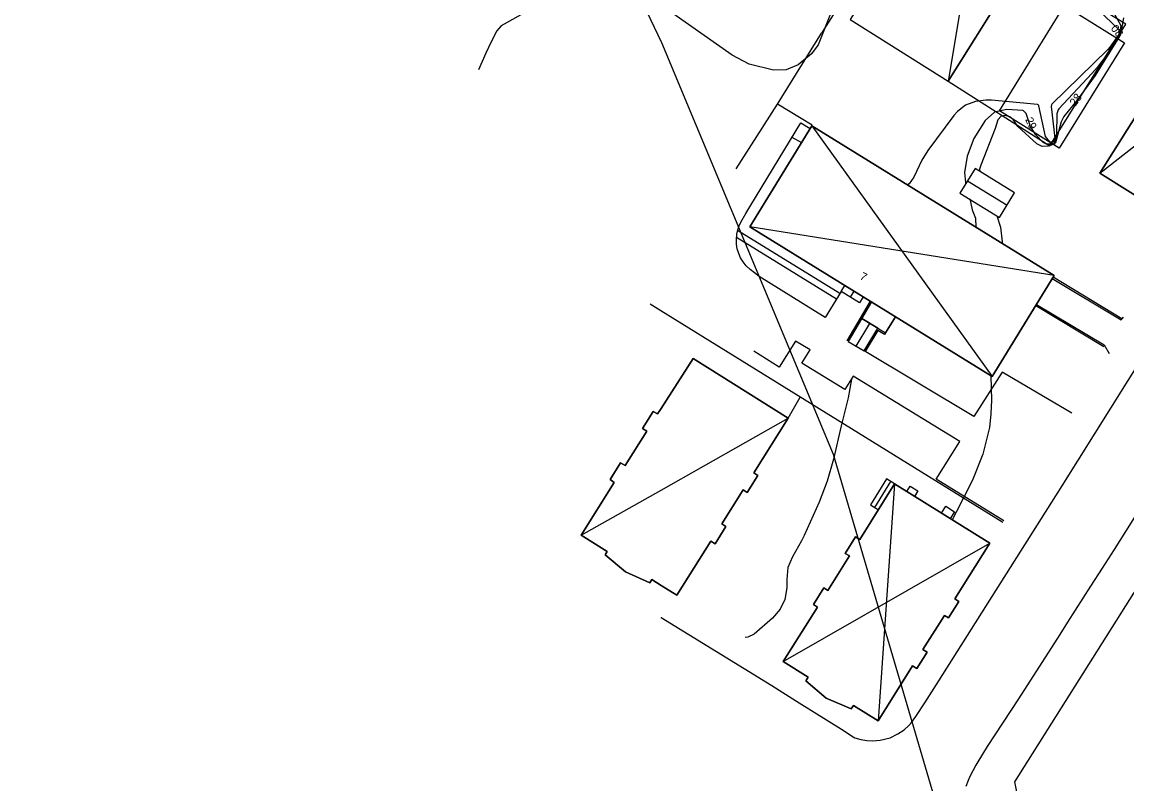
# Model space of a CAD drawing. Extents: x 67169 to 69652, y 20189 to 22818.
# Drawn here: x 69163.3 to 69301.4, y 21050.3 to 21145.5 of the extents above; entities that cross this region are included whole.
import ezdxf

# ---------------------------------------------------------------- set-up
doc = ezdxf.new("R2010")
doc.units = 0
for name, color, linetype in [('BYGGNAD_HUSLIV', 7, 'Continuous'), ('BYGGNAD_HUSLIV 11', 7, 'Continuous'), ('BYGGNADSDETALJER', 7, 'Continuous'), ('BYGGNADSDETALJER 19', 7, 'Continuous'), ('BYGGNADSSYMBOLER', 7, 'Continuous'), ('BYGGNADSSYMBOLER 30', 7, 'Continuous'), ('HOJDKURVOR_2014', 7, 'Continuous'), ('HOJDKURVOR_2014 5M', 7, 'Continuous'), ('HOJDKURVOR_TEXTER_2014', 7, 'Continuous'), ('Instruktioner', 7, 'Continuous'), ('JARNVAGAR', 7, 'Continuous'), ('MUR_STAKET', 7, 'Continuous'), ('MUR_STAKET_SYMBOL', 7, 'Continuous'), ('Std_Ritningsstämpel', 7, 'Continuous'), ('VAGAR 121', 7, 'Continuous'), ('VAGAR 123', 7, 'Continuous')]:
    doc.layers.add(name, color=color, linetype=linetype)

msp = doc.modelspace()

# ---------------------------------------------------------------- linework, layer by layer
at = {"layer": 'BYGGNAD_HUSLIV'}
msp.add_line((69242.68, 21096.53), (69242.99, 21096.96), dxfattribs=at)
for points in [[(69317.37, 21157.37), (69328.38, 21150.49), (69309.01, 21119.71), (69298, 21126.59), (69317.37, 21157.37)], [(69293.56, 21147.57), (69301.05, 21142.9), (69292.91, 21129.74), (69285.43, 21134.41), (69293.56, 21147.57)], [(69261.97, 21132.53), (69292.27, 21113.82), (69284.53, 21101.19), (69254.22, 21119.9), (69261.97, 21132.53)], [(69242.99, 21096.96), (69243.13, 21097.18), (69247.16, 21103.43), (69259.04, 21095.98), (69254.74, 21089.15), (69255.25, 21088.83), (69253.9, 21086.69), (69253.39, 21087.01), (69250.72, 21082.76), (69251.23, 21082.44), (69249.88, 21080.3), (69249.37, 21080.62), (69245.12, 21073.85), (69243.14, 21075.09)], [(69243.14, 21075.09), (69241.98, 21075.82), (69241.72, 21075.41), (69238.68, 21076.77), (69236.14, 21078.92), (69236.39, 21079.32), (69233.14, 21081.37), (69237.28, 21087.96), (69236.77, 21088.34), (69238.08, 21090.42), (69238.64, 21090.09), (69241.34, 21094.35), (69240.82, 21094.71), (69242.17, 21096.83), (69242.68, 21096.53)], [(69272.33, 21087.76), (69284.22, 21080.36), (69279.86, 21073.41), (69280.37, 21073.09), (69279.07, 21071.02), (69278.56, 21071.33), (69275.87, 21067.07), (69276.38, 21066.76), (69275.09, 21064.7), (69274.58, 21065.02), (69270.28, 21058.15), (69267.18, 21060.09), (69266.9, 21059.64), (69263.79, 21061.01), (69261.23, 21063.17), (69261.51, 21063.62), (69258.4, 21065.56), (69262.68, 21072.38), (69262.17, 21072.7), (69263.47, 21074.77), (69263.98, 21074.45), (69266.68, 21078.76), (69266.16, 21079.09), (69267.46, 21081.15), (69267.98, 21080.82), (69272.33, 21087.76)]]:
    msp.add_lwpolyline(points, dxfattribs=at)
at = {"layer": 'BYGGNAD_HUSLIV 11'}
msp.add_line((69242.68, 21096.53), (69242.99, 21096.96), dxfattribs=at)
for points in [[(69317.37, 21157.37), (69328.38, 21150.49), (69309.01, 21119.71), (69298, 21126.59), (69317.37, 21157.37)], [(69261.97, 21132.53), (69292.27, 21113.82), (69284.53, 21101.19), (69254.22, 21119.9), (69261.97, 21132.53)], [(69242.99, 21096.96), (69243.13, 21097.18), (69247.16, 21103.43), (69259.04, 21095.98), (69254.74, 21089.15), (69255.25, 21088.83), (69253.9, 21086.69), (69253.39, 21087.01), (69250.72, 21082.76), (69251.23, 21082.44), (69249.88, 21080.3), (69249.37, 21080.62), (69245.12, 21073.85), (69243.14, 21075.09)], [(69243.14, 21075.09), (69241.98, 21075.82), (69241.72, 21075.41), (69238.68, 21076.77), (69236.14, 21078.92), (69236.39, 21079.32), (69233.14, 21081.37), (69237.28, 21087.96), (69236.77, 21088.34), (69238.08, 21090.42), (69238.64, 21090.09), (69241.34, 21094.35), (69240.82, 21094.71), (69242.17, 21096.83), (69242.68, 21096.53)], [(69272.33, 21087.76), (69284.22, 21080.36), (69279.86, 21073.41), (69280.37, 21073.09), (69279.07, 21071.02), (69278.56, 21071.33), (69275.87, 21067.07), (69276.38, 21066.76), (69275.09, 21064.7), (69274.58, 21065.02), (69270.28, 21058.15), (69267.18, 21060.09), (69266.9, 21059.64), (69263.79, 21061.01), (69261.23, 21063.17), (69261.51, 21063.62), (69258.4, 21065.56), (69262.68, 21072.38), (69262.17, 21072.7), (69263.47, 21074.77), (69263.98, 21074.45), (69266.68, 21078.76), (69266.16, 21079.09), (69267.46, 21081.15), (69267.98, 21080.82), (69272.33, 21087.76)]]:
    msp.add_lwpolyline(points, dxfattribs=at)
at = {"layer": 'BYGGNADSDETALJER'}
msp.add_line((69266.11, 21112.56), (69268.4, 21111.14), dxfattribs=at)
for points in [[(69268.4, 21111.14), (69267.94, 21110.42), (69265.64, 21111.82), (69266.11, 21112.56)], [(69269.42, 21110.51), (69266.54, 21105.55), (69268.51, 21104.39), (69270.23, 21107.22), (69268.22, 21108.45)], [(69268.22, 21108.45), (69271.18, 21106.64), (69272.45, 21108.64)], [(69270.3, 21084.53), (69272.33, 21087.76), (69271.32, 21088.4), (69269.3, 21085.14), (69270.3, 21084.53)], [(69274.83, 21086.21), (69273.84, 21086.82), (69274.26, 21087.48), (69275.24, 21086.89), (69274.83, 21086.21)], [(69279.28, 21083.43), (69278.17, 21084.12), (69278.73, 21084.97), (69279.82, 21084.3), (69279.28, 21083.43)]]:
    msp.add_lwpolyline(points, dxfattribs=at)
at = {"layer": 'BYGGNADSDETALJER 19'}
msp.add_lwpolyline([(69268.22, 21108.45), (69271.18, 21106.64), (69272.45, 21108.64)], dxfattribs=at)
at = {"layer": 'BYGGNADSSYMBOLER'}
for p, q in [((69285.23, 21175.26), (69279.02, 21138.12)), ((69298, 21126.59), (69328.38, 21150.49)), ((69261.97, 21132.53), (69284.53, 21101.19)), ((69281.44, 21125.66), (69286.38, 21122.61)), ((69292.27, 21113.82), (69254.22, 21119.9)), ((69267.25, 21111.85), (69266.79, 21111.12)), ((69267.25, 21111.85), (69267.25, 21111.85)), ((69267.52, 21104.97), (69269.23, 21107.83)), ((69267.52, 21104.97), (69267.52, 21104.97)), ((69271.83, 21088.08), (69269.8, 21084.83)), ((69272.33, 21087.76), (69270.28, 21058.15)), ((69271.83, 21088.08), (69271.83, 21088.08)), ((69258.4, 21065.56), (69284.22, 21080.36))]:
    msp.add_line(p, q, dxfattribs=at)
msp.add_lwpolyline([(69233.15, 21081.36), (69243.13, 21087), (69259.04, 21095.98)], dxfattribs=at)
at = {"layer": 'BYGGNADSSYMBOLER 30'}
for p, q in [((69285.23, 21175.26), (69279.02, 21138.12)), ((69298, 21126.59), (69328.38, 21150.49)), ((69261.97, 21132.53), (69284.53, 21101.19)), ((69292.27, 21113.82), (69254.22, 21119.9)), ((69272.33, 21087.76), (69270.28, 21058.15)), ((69258.4, 21065.56), (69284.22, 21080.36))]:
    msp.add_line(p, q, dxfattribs=at)
msp.add_lwpolyline([(69233.15, 21081.36), (69243.13, 21087), (69259.04, 21095.98)], dxfattribs=at)
at = {"layer": 'HOJDKURVOR_2014'}
for points in [[(69264.48, 21146.95), (69262.78, 21142.63), (69261.92, 21141.51), (69260.26, 21140.16), (69258.79, 21139.51), (69257.18, 21139.46), (69254.13, 21140.22), (69252.02, 21141.37), (69243.06, 21147.63)], [(69298.72, 21148.49), (69300.61, 21145.06), (69300.44, 21143.9), (69298.85, 21141.39), (69297.64, 21139.82), (69296.99, 21139.07), (69292.87, 21134.63), (69292.78, 21134.53), (69292.59, 21134.04), (69292.57, 21131.47), (69292.34, 21130.49), (69292.28, 21130.41), (69291.78, 21130.24), (69291.31, 21130.22), (69290.89, 21130.44), (69289.97, 21131.41), (69289.33, 21132.43), (69288.76, 21134.06), (69288.45, 21134.39), (69288.35, 21134.44), (69286.35, 21134.56), (69284.83, 21134.22), (69283.66, 21133.19), (69282.22, 21130.94), (69281.4, 21128.75), (69281.05, 21126.69), (69281.2, 21125.44), (69281.23, 21125.31)], [(69225.63, 21146.39), (69223.16, 21145.01), (69222.62, 21144.41), (69221.91, 21143.03), (69221.24, 21141.62), (69220.33, 21139.54)], [(69300.95, 21146.01), (69300.59, 21144.09), (69300.46, 21143.74), (69300.4, 21143.63), (69298.08, 21139.9), (69297.38, 21138.81), (69295.09, 21135.7), (69293.47, 21133.68), (69293.15, 21133.03), (69292.42, 21130.41), (69292.41, 21130.39), (69292.3, 21130.25), (69292.28, 21130.25), (69291.52, 21129.99), (69290.78, 21129.95), (69290.12, 21130.29), (69287.75, 21132.45), (69287.15, 21133.31), (69286.72, 21133.66), (69286.2, 21133.82), (69285.65, 21133.75), (69285.22, 21133.26), (69284.88, 21132.17), (69283.1, 21127.59), (69282.95, 21127.1), (69282.96, 21126.83)], [(69281.71, 21123.38), (69282.04, 21122.02), (69282.44, 21120.97), (69282.47, 21119.87)], [(69285.12, 21121.27), (69285.57, 21119.85), (69285.78, 21118.04), (69285.78, 21117.83)], [(69266.92, 21100.84), (69266.51, 21098.52), (69265.65, 21095.04), (69264.67, 21090.86), (69263.91, 21088.12), (69262.88, 21085.47), (69261.02, 21081.34), (69260.69, 21080.65), (69259.58, 21078.66), (69259, 21077.31), (69258.84, 21075.84), (69258.86, 21074.76), (69258.6, 21073.32), (69258.04, 21072.1), (69257.05, 21070.98), (69254.79, 21068.98), (69253.99, 21068.63), (69253.64, 21068.59)], [(69284.37, 21101.29), (69284.42, 21098.25), (69284.36, 21096.53), (69284.18, 21094.82), (69283.34, 21091.49), (69282.07, 21088.25), (69280.06, 21084.32), (69279.52, 21083.29)]]:
    msp.add_lwpolyline(points, dxfattribs=at)
at = {"layer": 'HOJDKURVOR_2014 5M'}
msp.add_lwpolyline([(69297.82, 21146.97), (69300.31, 21144.61), (69300.42, 21144.42), (69300.43, 21144.19), (69300.37, 21143.93), (69299.25, 21142.36), (69298.98, 21142.07), (69292, 21135.25), (69291.93, 21135.16), (69291.89, 21134.93), (69292.36, 21131), (69292.28, 21130.6), (69292.25, 21130.57), (69291.93, 21130.48), (69291.75, 21130.53), (69291.19, 21131.17), (69290.37, 21135.04), (69290.36, 21135.06), (69290.26, 21135.15), (69290.17, 21135.18), (69284.42, 21135.71), (69283.75, 21135.73), (69282.44, 21135.56), (69281.2, 21135.09), (69280.17, 21134.32), (69279.73, 21133.82), (69276.49, 21129.43), (69275.73, 21128.24), (69274.72, 21126.11), (69274.16, 21125.26), (69273.96, 21125.13)], dxfattribs=at)
at = {"layer": 'JARNVAGAR'}
msp.add_lwpolyline([(69162.71, 21269.58), (69192.52, 21230.99), (69216.76, 21192.72), (69236.42, 21157.17), (69243.2, 21142.94), (69264.66, 21091.47), (69285.76, 21019.69), (69301.99, 20965.18), (69320.92, 20901.49), (69337.69, 20844.28)], dxfattribs=at)
at = {"layer": 'MUR_STAKET'}
for p, q in [((69284.59, 21177.99), (69263.19, 21144.09)), ((69262.01, 21132.59), (69257.69, 21135.25)), ((69269.26, 21110.61), (69266.37, 21105.64)), ((69269.26, 21110.61), (69266.37, 21105.64)), ((69289.96, 21110.05), (69298.49, 21104.96)), ((69272.45, 21108.64), (69271.18, 21106.64))]:
    msp.add_line(p, q, dxfattribs=at)
for points in [[(69252.51, 21127.15), (69257.69, 21135.25), (69263.19, 21144.09)], [(69300.88, 21108.61), (69300.75, 21108.41), (69292.14, 21113.6)], [(69285.85, 21082.93), (69243.11, 21109.4), (69241.77, 21110.23)], [(69272.45, 21108.64), (69271.18, 21106.64), (69271.06, 21106.44), (69270.23, 21106.93), (69268.64, 21104.32)], [(69271.32, 21088.4), (69269.3, 21085.14), (69270.3, 21084.53)], [(69271.32, 21088.4), (69269.3, 21085.14), (69270.3, 21084.53)], [(69322.79, 21025.8), (69287.95, 21047.64), (69287.36, 21050.54), (69309.75, 21086.07)]]:
    msp.add_lwpolyline(points, dxfattribs=at)
at = {"layer": 'MUR_STAKET_SYMBOL'}
for p, q in [((69260.66, 21140.03), (69260.66, 21140.03)), ((69260.41, 21133.57), (69260.41, 21133.57)), ((69255.12, 21131.22), (69255.12, 21131.22)), ((69268.67, 21109.59), (69268.67, 21109.59)), ((69290.87, 21109.51), (69290.87, 21109.51)), ((69267.89, 21108.26), (69267.89, 21108.26)), ((69272.04, 21107.99), (69272.04, 21107.99)), ((69272.07, 21108.03), (69272.07, 21108.03)), ((69292.12, 21108.76), (69292.12, 21108.76)), ((69293.35, 21108.02), (69293.35, 21108.02)), ((69248.12, 21106.29), (69248.12, 21106.29)), ((69267.14, 21106.96), (69267.14, 21106.96)), ((69267.23, 21107.12), (69267.23, 21107.12)), ((69270.68, 21106.66), (69270.68, 21106.66)), ((69271.39, 21106.97), (69271.39, 21106.97)), ((69294.68, 21107.23), (69294.68, 21107.23)), ((69295.97, 21106.47), (69295.97, 21106.47)), ((69266.37, 21105.64), (69266.37, 21105.64)), ((69269.48, 21105.7), (69269.48, 21105.7)), ((69297.25, 21105.7), (69297.25, 21105.7)), ((69298.49, 21104.96), (69298.49, 21104.96)), ((69264.2, 21096.33), (69264.2, 21096.33)), ((69270.3, 21086.76), (69270.3, 21086.76)), ((69271.09, 21088.04), (69271.09, 21088.04)), ((69269.55, 21085.53), (69269.55, 21085.53)), ((69270.09, 21086.42), (69270.09, 21086.42)), ((69279.79, 21086.67), (69279.79, 21086.67)), ((69269.58, 21084.96), (69269.58, 21084.96)), ((69300.71, 21071.74), (69300.71, 21071.74)), ((69299.94, 21070.51), (69299.94, 21070.51)), ((69299.12, 21069.21), (69299.12, 21069.21)), ((69298.32, 21067.94), (69298.32, 21067.94)), ((69297.56, 21066.73), (69297.56, 21066.73)), ((69296.73, 21065.41), (69296.73, 21065.41)), ((69295.95, 21064.17), (69295.95, 21064.17)), ((69295.13, 21062.88), (69295.13, 21062.88)), ((69294.33, 21061.61), (69294.33, 21061.61)), ((69293.55, 21060.36), (69293.55, 21060.36)), ((69292.03, 21057.96), (69292.03, 21057.96)), ((69292.73, 21059.06), (69292.73, 21059.06)), ((69291.27, 21056.76), (69291.27, 21056.76)), ((69290.45, 21055.46), (69290.45, 21055.46)), ((69289.66, 21054.2), (69289.66, 21054.2)), ((69288.84, 21052.89), (69288.84, 21052.89)), ((69288.05, 21051.65), (69288.05, 21051.65))]:
    msp.add_line(p, q, dxfattribs=at)
at = {"layer": 'Std_Ritningsstämpel'}
for points in [[(69266.76, 21145.82), (69279.02, 21138.11), (69297.52, 21167.57), (69285.23, 21175.26)], [(69317.37, 21157.37), (69298, 21126.59), (69309.01, 21119.71), (69328.38, 21150.49)], [(69279.02, 21138.11), (69291.73, 21130.03), (69301.23, 21145.21), (69288.39, 21153.08)], [(69261.97, 21132.53), (69254.22, 21119.9), (69284.53, 21101.19), (69292.27, 21113.82)], [(69282.39, 21127.19), (69280.5, 21124.12), (69285.43, 21121.08), (69287.32, 21124.14)], [(69243.13, 21097.18), (69242.99, 21096.96), (69242.68, 21096.53), (69242.17, 21096.83), (69240.82, 21094.71), (69241.34, 21094.35), (69238.64, 21090.09), (69238.08, 21090.42), (69236.77, 21088.34), (69237.28, 21087.96), (69233.14, 21081.37), (69236.39, 21079.32), (69236.14, 21078.92), (69238.68, 21076.77), (69241.72, 21075.41), (69241.98, 21075.82), (69243.14, 21075.09), (69245.12, 21073.85), (69249.37, 21080.62), (69249.88, 21080.3), (69251.23, 21082.44), (69250.72, 21082.76), (69253.39, 21087.01), (69253.9, 21086.69), (69255.25, 21088.83), (69254.74, 21089.15), (69259.04, 21095.98), (69247.16, 21103.43)], [(69272.33, 21087.76), (69267.98, 21080.82), (69267.46, 21081.15), (69266.16, 21079.09), (69266.68, 21078.76), (69263.98, 21074.45), (69263.47, 21074.77), (69262.17, 21072.7), (69262.68, 21072.38), (69258.4, 21065.56), (69261.51, 21063.62), (69261.23, 21063.17), (69263.79, 21061.01), (69266.9, 21059.64), (69267.18, 21060.09), (69270.28, 21058.15), (69274.58, 21065.02), (69275.09, 21064.7), (69276.38, 21066.76), (69275.87, 21067.07), (69278.56, 21071.33), (69279.07, 21071.02), (69280.37, 21073.09), (69279.86, 21073.41), (69284.22, 21080.36)]]:
    msp.add_lwpolyline(points, close=True, dxfattribs=at)
at = {"layer": 'VAGAR 121'}
for p, q in [((69260.59, 21132.91), (69261.76, 21132.19)), ((69259.5, 21131.11), (69260.68, 21130.42)), ((69259.04, 21095.98), (69260.53, 21098.61))]:
    msp.add_line(p, q, dxfattribs=at)
for points in [[(69265.64, 21111.82), (69263.63, 21108.55), (69255.39, 21113.71), (69254.81, 21114.15), (69254.28, 21114.55), (69253.77, 21115.02), (69253.39, 21115.51), (69253.08, 21116.04), (69252.85, 21116.56), (69252.67, 21117.16), (69252.58, 21117.73), (69252.55, 21118.26), (69252.6, 21118.98), (69252.72, 21119.52), (69252.88, 21120.02), (69253.09, 21120.5), (69253.73, 21121.57), (69254.36, 21122.62), (69260.59, 21132.91)], [(69292.03, 21113.43), (69300.65, 21108.27), (69300.75, 21108.41)], [(69290.05, 21110.2), (69298.54, 21105.16), (69299.15, 21104.05)], [(69285.98, 21083.14), (69277.52, 21088.37), (69280.47, 21093.08), (69267.16, 21101.22), (69266.12, 21099.57), (69260.75, 21102.88), (69261.77, 21104.53), (69259.95, 21105.61), (69257.88, 21102.35), (69254.73, 21104.35)], [(69243.15, 21071.1), (69243.15, 21071.09), (69256.97, 21062.57), (69260.07, 21060.61), (69266.03, 21056.9), (69266.95, 21056.27), (69267.36, 21056.04), (69268.09, 21055.84), (69268.87, 21055.7), (69269.61, 21055.65), (69270.51, 21055.74), (69271.76, 21056.05), (69272.75, 21056.52), (69273.51, 21057.04), (69274.1, 21057.59), (69274.45, 21057.97), (69275, 21058.68), (69276.12, 21060.39), (69277.85, 21063.15), (69285.51, 21075.27), (69293.27, 21087.54), (69303.5, 21103.83)], [(69294.47, 21096.61), (69285.76, 21101.73), (69282.25, 21096.19), (69268.51, 21104.39)], [(69303.53, 21085.53), (69299.76, 21079.59), (69298.27, 21077.25), (69296.8, 21074.99), (69294.91, 21072.01), (69293.94, 21070.47), (69292.96, 21068.94), (69287.82, 21060.91), (69283.9, 21054.96), (69282.73, 21053.05), (69282.46, 21052.62), (69282.09, 21051.92), (69281.75, 21051.21), (69281.52, 21050.69), (69281.25, 21049.96)]]:
    msp.add_lwpolyline(points, dxfattribs=at)
at = {"layer": 'VAGAR 123'}
for p, q in [((69252.57, 21118.6), (69265.07, 21110.9)), ((69265.48, 21111.57), (69252.69, 21119.42))]:
    msp.add_line(p, q, dxfattribs=at)

# ---------------------------------------------------------------- texts
at = {"layer": 'HOJDKURVOR_TEXTER_2014'}
for s, rotation, p in [('30', 129.3385, (69301, 21144.14)), ('28', 53.1004, (69294.91, 21134.9)), ('29', 295.2248, (69288.62, 21133.31))]:
    msp.add_text(s, height=1, rotation=rotation, dxfattribs=at).set_placement(p)
at = {"layer": 'Instruktioner'}
msp.add_text('7', height=1, rotation=331.9473, dxfattribs=at).set_placement((69267.89, 21113.41))

doc.saveas('drawing.dxf')
